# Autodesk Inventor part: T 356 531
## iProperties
_DisabledCommands: 0
Created: 2005-12
Part Number: T 356 531
Material: 1.4301
Description: Bolzen
Vendor: Autodesk Inc.
Document SubType Name: Modeling
Standard: DIN 671
Designer: I.Baliuc
Size Designation: 10 - 84
Density: 7.86 g/cm^3
HalbzeugNorm: DIN 671
Abmessung: Rd 10 - 84
Author: T.Messerschmitt
Keywords: 266187
Revision Number: 356531
Comments: DIN 671 / 10 - 84
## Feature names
1. Körper [Extrusion]
2. Bohrung_M6x10_L [Hole]
3. Bohrung_M6x10_R [Hole]
